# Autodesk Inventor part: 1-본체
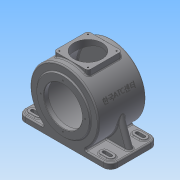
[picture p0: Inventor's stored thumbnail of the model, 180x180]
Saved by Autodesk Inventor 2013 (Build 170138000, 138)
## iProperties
Created: 2015-06
Part Number: 1-본체
Material: 일반
Document SubType Name: Modeling
Designer: ST3
Density: 1 g/cm^3
Author: ST3
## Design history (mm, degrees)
sketch "스케치1"
  geometry: C1 r 85 at (0, 0); 1 further point
  constraints: 1 centre point, 1 coincident
  dimensions: "d0" = 170 diameter of C1
extrude "돌출1" new body sketch "스케치1" distance "d2" = 118; taper "d3" = 0 deg
node "작업 평면1"
node "작업 평면3"
sketch "스케치4"
  geometry: L1 (42.5, 16.5)-(-42.5, 16.5); L2 (-42.5, 16.5)-(-42.5, 101.5); L3 (-42.5, 101.5)-(42.5, 101.5); L4 (42.5, 101.5)-(42.5, 16.5); L5 (85, 118)-(-85, 118) reference; L6 (-85, 0)-(85, 0) reference; L7 (-85, 0)-(-85, 118) reference; L8 (85, 0)-(85, 118) reference; 5 further points
  constraints: 8 end point, 4 midpoint, 2 parallel, 1 horizontal, 1 horizontal alignment, 1 perpendicular, 1 vertical alignment
  dimensions: "d13" = 85 distance of L1.start L1.end; "d15" = 85 distance of L3.end L1.start
extrude "돌출3" join sketch "스케치4" stored distance "d16" = 88; taper "d17" = 0 deg
sketch "스케치5"
  geometry: L1 (-42.5, -16.5)-(42.5, -16.5) reference; L2 (-42.5, -101.5)-(-42.5, -16.5) reference; C1 r 35 at (0, -59); 3 further points
  constraints: 2 midpoint, 1 centre point, 1 horizontal alignment, 1 vertical alignment
  dimensions: "d18" = 70 diameter of C1
sketch "스케치6"
  geometry: A1 r 50.205 centre (0, -59) between (-35.5, -23.5) and (35.5, -23.5); 3 further points
  constraints: 4 point on circle, 2 horizontal alignment, 2 vertical alignment, 1 centre point
  dimensions: "d22" = 71 distance of A1.end A1.start; "d24" = 71 distance of point (-35.5, -94.5) A1.start
hole "구멍1" sketch "스케치6" at (-35.5, -23.5), (35.5, -23.5), (-35.5, -94.5), (35.5, -94.5) diameter "d25" = 3.242; stored, may be unused: countersink angle "d29" = 90 deg, drill point angle "d31" = 118 deg; dims "d26" = 10, "d27" = 4, "d28" = 2, "d30" = 13
node "작업 평면7"
sketch "스케치7"
  geometry: L1 (-42.5, 101.5)-(-42.5, 16.5) reference; L2 (-42.5, 16.5)-(42.5, 16.5) reference; L3 (42.5, 16.5)-(42.5, 101.5) reference; L4 (42.5, 101.5)-(-42.5, 101.5) reference; L5 (85, 118)-(-85, 118) reference; L6 (-85, 0)-(85, 0) reference; L7 (-85, 118)-(-115, 118); L8 (-115, 118)-(-115, 0); L9 (-115, 0)-(-85, 0); L10 (85, 0)-(115, 0); L11 (115, 0)-(115, 118); L12 (115, 118)-(85, 118); 2 further points
  constraints: 12 end point, 2 horizontal, 2 parallel, 1 midpoint, 1 perpendicular, 1 vertical
  dimensions: "d35" = 230 distance between parallel lines of L11 L8; "d37" = 115 distance from line of L11 point (0, 118)
extrude "돌출5" join sketch "스케치7" distance "d38" = 14; taper "d39" = 0 deg
sketch "스케치2"
  geometry: C1 r 77 at (0, 0); 1 further point
  constraints: 1 centre point, 1 coincident
  dimensions: "d4" = 154 diameter of C1
extrude "돌출2" cut sketch "스케치2" stored distance "d6" = 102; taper "d7" = 0 deg
extrude "돌출6" cut sketch "스케치5" stored distance "d40" = 14; taper "d41" = 0 deg
sketch "스케치8"
  geometry: C1 r 65 at (0, 0); A1 r 85 centre (0, 0) between (46.733, -71) and (-46.733, -71) reference
  constraints: 1 centre point, 1 coincident
  dimensions: "d42" = 130 diameter of C1
extrude "돌출7" join sketch "스케치8" distance "d44" = 3; taper "d45" = 0 deg
sketch "스케치9"
  geometry: C1 r 65 at (0, 0); A1 r 85 centre (0, 0) between (46.733, -71) and (-46.733, -71) reference
  constraints: 1 centre point, 1 coincident
  dimensions: "d46" = 130 diameter of C1
extrude "돌출8" join sketch "스케치9" distance "d48" = 13; taper "d49" = 0 deg
sketch "스케치13"
  geometry: C1 r 65 at (0, 0) reference; C2 r 47.5 at (0, 0)
  constraints: 1 centre point, 1 coincident
  dimensions: "d63" = 95 diameter of C2
extrude "돌출9" cut sketch "스케치13" stored distance "d65" = 13; taper "d66" = 0 deg
sketch "스케치14"
  geometry: C1 r 77 at (0, 0) reference; C2 r 31 at (0, 0)
  constraints: 1 centre point, 1 coincident
  dimensions: "d67" = 62 diameter of C2
extrude "돌출10" join sketch "스케치14" distance "d69" = 3.5; taper "d70" = -25 deg
sketch "스케치16"
  geometry: C1 r 29.368 at (0, 0) reference; C2 r 23.5 at (0, 0); C3 r 15 at (0, 0)
  constraints: 2 centre point, 2 coincident
  dimensions: "d71" = 47 diameter of C2; "d73" = 30 diameter of C3
extrude "돌출11" cut sketch "스케치16" distance "d74" = 14; taper "d75" = 0 deg
extrude "돌출12" cut sketch "스케치16" distance "d76" = 17; taper "d77" = 0 deg
sketch "스케치17"
  geometry: C1 r 47.5 at (0, 0) reference; C2 r 65 at (0, 0) reference; A1 r 55 centre (0, 0) between (0, 55) and (-55, 0); 2 further points
  constraints: 4 point on circle, 2 horizontal alignment, 2 vertical alignment, 1 centre point, 1 coincident
  dimensions: "d78" = 110 diameter of A1
hole "구멍2" sketch "스케치17" at (0, 55), (-55, 0), (55, 0), (0, -55) diameter "d80" = 3.242; stored, may be unused: countersink angle "d84" = 90 deg, drill point angle "d86" = 118 deg; dims "d81" = 10, "d82" = 4, "d83" = 2, "d85" = 13
node "작업 평면12"
sketch "스케치19"
  geometry: L1 (0, 0)-(77.036, 35.923); L2 (0, 0)-(23.5, 0); C1 r 15 at (0, 0) reference; A1 r 85 centre (0, 0) between (46.733, -71) and (-46.733, -71) reference
  constraints: 4 end point, 1 horizontal, 1 horizontal alignment, 1 point on circle, 1 other
  dimensions: "d87" = 25 deg angle of L2 L1
  node "투영된 루프7"
node "작업 평면13"
sketch "스케치20"
  geometry: 5 further points
  constraints: 1 coincident, 1 other
feature "엠보싱1" sketch "스케치20" dims "d88" = 0.5, "d89" = 0
sketch "스케치21"
  geometry: L1 (-115, 0)-(-115, -118) reference; L2 (-115, -118)-(-46.733, -118) reference; L3 (-97, -9)-(-81, -9); L4 (-97, -27)-(-81, -27); L5 (81, -9)-(97, -9); L6 (81, -27)-(97, -27); L7 (81, -91)-(97, -91); L8 (81, -91)-(97, -91); L9 (-97, -91)-(-81, -91); L10 (-97, -109)-(-81, -109); L11 (81, -109)-(97, -109); A1 r 9 centre (-97, -18) between (-97, -9) and (-97, -27); A2 r 9 centre (-81, -18) between (-81, -9) and (-81, -27); A3 r 9 centre (-97, -100) between (-97, -91) and (-97, -109); A4 r 9 centre (-81, -100) between (-81, -91) and (-81, -109); A5 r 9 centre (81, -18) between (81, -9) and (81, -27); A6 r 9 centre (97, -18) between (97, -9) and (97, -27); A7 r 9 centre (81, -100) between (81, -91) and (81, -91); A8 r 9 centre (97, -100) between (97, -91) and (97, -91); 2 further points
  constraints: 18 end point, 18 point on circle, 13 tangent, 8 centre point, 7 equal radius, 6 horizontal alignment, 4 vertical alignment, 3 parallel, 2 collinear, 1 midpoint
  dimensions: "d90" = 16 distance of A2.centre A1.centre; "d92" = 16 distance of A6.centre A5.centre; "d93" = 82 distance of A3.centre A1.centre; "d94" = 41 vertical distance of point (-115, -59) A1.centre; "d95" = 194 distance of A6.centre A1.centre; "d96" = 18 diameter of A1; "d97" = 97 horizontal distance of point (0, 0) A1.centre
extrude "돌출13" join sketch "스케치21" distance "d98" = 3; taper "d99" = 0 deg
sketch "스케치22"
  geometry: L1 (-81, -91)-(-97, -91) reference; L2 (-97, -109)-(-81, -109) reference; L3 (115, -118)-(-115, -118) reference; L4 (-115, -118)-(-115, 0) reference; L5 (-115, 0)-(115, 0) reference; L6 (115, 0)-(115, -118) reference; L7 (-97, -9)-(-81, -9) reference; L8 (-81, -27)-(-97, -27) reference; L9 (81, -91)-(97, -91) reference; L10 (97, -109)-(81, -109) reference; L11 (81, -9)-(97, -9) reference; L12 (97, -27)-(81, -27) reference; L13 (97, -14)-(81, -14); L14 (81, -22)-(97, -22); L15 (97, -96)-(81, -96); L16 (81, -104)-(97, -104); L17 (-97, -96)-(-81, -96); L18 (-81, -104)-(-97, -104); L19 (-81, -14)-(-97, -14); L20 (-97, -22)-(-81, -22); A1 r 9 centre (-97, -100) between (-97, -91) and (-97, -109) reference; A2 r 9 centre (-81, -100) between (-81, -109) and (-81, -91) reference; A3 r 9 centre (-97, -18) between (-97, -9) and (-97, -27) reference; A4 r 9 centre (-81, -18) between (-81, -27) and (-81, -9) reference; A5 r 9 centre (81, -100) between (81, -91) and (81, -109) reference; A6 r 9 centre (97, -100) between (97, -109) and (97, -91) reference; A7 r 9 centre (81, -18) between (81, -9) and (81, -27) reference; A8 r 9 centre (97, -18) between (97, -27) and (97, -9) reference; A9 r 4 centre (81, -18) between (81, -14) and (81, -22); A10 r 4 centre (97, -18) between (97, -22) and (97, -14); A11 r 4 centre (81, -100) between (81, -96) and (81, -104); A12 r 4 centre (97, -100) between (97, -104) and (97, -96); A13 r 4 centre (-81, -100) between (-81, -104) and (-81, -96); A14 r 4 centre (-97, -100) between (-97, -96) and (-97, -104); A15 r 4 centre (-97, -18) between (-97, -14) and (-97, -22); A16 r 4 centre (-81, -18) between (-81, -22) and (-81, -14); 1 further point
  constraints: 16 end point, 16 point on circle, 8 centre point, 12 other
  dimensions: "d101" = 8 distance between parallel lines of L20 L19; "d103" = 8 distance between parallel lines of L18 L17; "d104" = 8 distance between parallel lines of L16 L15; "d105" = 8 distance between parallel lines of L14 L13
extrude "돌출14" cut sketch "스케치22" stored distance "d106" = 3; taper "d107" = 0 deg
node "작업 평면15"
sketch "스케치23"
  geometry: L1 (115, -71)-(46.733, -71) reference; L2 (115, -85)-(115, -71) reference; L3 (-115, -85)-(115, -85) reference; L4 (-115, -85)-(-115, -71) reference; L5 (-46.733, -71)-(-115, -71) reference; L6 (-109, -71)-(-84.87, -4.703); L7 (84.87, -4.703)-(109, -71); C1 r 65 at (0, 0) reference; A1 r 85 centre (0, 0) between (46.733, -71) and (-46.733, -71) reference; 1 further point
  constraints: 4 end point, 2 point on circle, 2 point on line
  dimensions: "d109" = 6 distance of L4.end L6.start; "d110" = 6 distance of L1.start L7.end; "d111" = 110 deg angle of L5 L6; "d112" = 110 deg angle of L1 L7
  node "투영된 루프9"
feature "리브1" dims "d113" = 1, "d114" = 15, "d115" = 0, "d116" = 0, "d117" = 1, "d118" = 1
feature "리브2" dims "d119" = 1, "d120" = 15, "d121" = 0, "d122" = 0, "d123" = 1, "d124" = 1
fillet "모깎기1" dims "d125" = 18
fillet "모깎기2" dims "d126" = 0.3
fillet "모깎기3" dims "d127" = 3
chamfer "모따기1" distance "d128" = 1; stored, may be unused: second distance "d129" = 2, angle "d130" = 45 deg
fillet "모깎기4" dims "d131" = 7.5
fillet "모깎기5" dims "d132" = 3
fillet "모깎기6" dims "d133" = 7
fillet "모깎기7" dims "d134" = 3
fillet "모깎기8" dims "d135" = 3
fillet "모깎기9" dims "d136" = 3
fillet "모깎기10" dims "d137" = 3
fillet "모깎기11" dims "d138" = 3
fillet "모깎기12" dims "d139" = 3
node "솔리드1"
node "투영된 루프2"
node "투영된 루프3"
node "투영된 루프8"
other parameters: "d12" = 88, "d34" = -85, "d108" = -59
